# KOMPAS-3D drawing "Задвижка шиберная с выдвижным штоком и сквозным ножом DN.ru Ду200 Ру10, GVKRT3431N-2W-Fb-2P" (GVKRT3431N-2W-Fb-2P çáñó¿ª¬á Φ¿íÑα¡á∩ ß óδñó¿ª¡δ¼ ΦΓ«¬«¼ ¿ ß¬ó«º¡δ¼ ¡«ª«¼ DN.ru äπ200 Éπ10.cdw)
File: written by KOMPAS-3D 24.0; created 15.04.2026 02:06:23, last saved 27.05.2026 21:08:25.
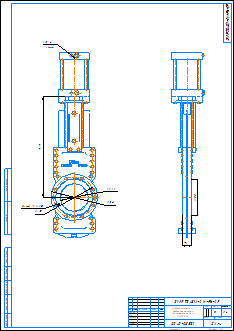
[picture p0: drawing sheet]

Document properties: Автор: DN.ru; Форматы листов документа: A2; Полное имя файла: GVKRT3431N-2W-Fb-2P Задвижка шиберная с выдвижным штоком и сквозным ножом DN.ru Ду200 Ру10.m3d; Масса: 50; Наименование: Задвижка шиберная с выдвижным штоком и сквозным ножом DN.ru Ду200 Ру10; Количество листов документа: 1; Примечание: D040-08532

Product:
- Part/product: Задвижка шиберная с выдвижным штоком и сквозным ножом DN.ru Ду200 Ру10  | designation GVKRT3431N-2W-Fb-2P
    Масса: 50
    Раздел спецификации: Прочие изделия
    Примечание: D040-08532

Views: Вид 1, Вид:1, Проекционный вид 2
Referenced files in C:\Работа\GVKRT3431N-2W-Fb-2P Задвижка шиберная со сквозным ножом DN.ru Ду100-250 Ру16\DN100\: GVKRT3431N-2W-Fb-2P Задвижка шиберная со сквозным ножом DN.ru Ду100 Ру16.m3d
Referenced files in C:\Работа\ГОТОВЫЕ ИСХОДНИКИ\GVKRT3431N-2W-Fb-2P Задвижка шиберная со сквозным ножом DN.ru Ду100-250 Ру16\DN200\: GVKRT3431N-2W-Fb-2P Задвижка шиберная с выдвижным штоком и сквозным ножом DN.ru Ду200 Ру10.m3d
Referenced files in C:\Program Files\ASCON\KOMPAS-3D v24\Templates\: Чертеж_DN.ru.cdt
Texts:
  GVKRT3431N-2W-Fb-2P
  Чертеж_DN.ru.cdt
  Задвижка шиберная с
  выдвижным штоком и
  сквозным ножом DN.ru
  Ду200 Ру10
  Задвижка шиберная с выдвижным штоком и сквозным ножом DN.ru Ду200 Ру10
  GVKRT3431N-2W-Fb-2P Задвижка шиберная с выдвижным штоком и сквозным ножом DN.ru Ду200 Ру10
Dimensions and other numbers on the sheet: 0; 3; 2; 4; 727; 295; 340; 200; 2 места; 8 отв.; 20; 8; 70; 266; 1:4; 1; 50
